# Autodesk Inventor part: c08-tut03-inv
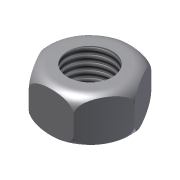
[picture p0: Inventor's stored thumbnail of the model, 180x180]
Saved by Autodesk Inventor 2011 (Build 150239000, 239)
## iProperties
Created: 2010-03
Part Number: c08-tut03-inv
Document SubType Name: Modeling
Designer: CADSoft
Density: 1 g/cm^3
Author: CADSoft
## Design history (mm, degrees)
sketch "Sketch1"
  geometry: C1 r 10 at (0, 0); 1 further point
  constraints: 1 centre point, 1 coincident
  dimensions: "d0" = 20 diameter of C1
extrude "Extrusion1" new body sketch "Sketch1" distance "d1" = 10; taper "d2" = 0 deg
hole "Hole1" diameter "d5" = 10; stored, may be unused: countersink angle "d9" = 90 deg, drill point angle "d11" = 118 deg; dims "d3" = 10, "d4" = 10, "d6" = 6, "d7" = 4, "d8" = 2, "d10" = 8
fillet "Fillet1" dims "d12" = 3, "d13" = 3
sketch "Sketch2"
  geometry: L1 (-10, 0)-(-5, 8.66); L2 (-5, 8.66)-(5, 8.66); L3 (5, 8.66)-(10, 0); L4 (10, 0)-(5, -8.66); L5 (5, -8.66)-(-5, -8.66); L6 (-5, -8.66)-(-10, 0); C1 r 5 at (0, 0); 1 further point
  constraints: 12 end point, 1 centre point, 1 coincident, 13 other
  dimensions: "d19" = 10 diameter of C1
extrude "Extrusion4" sketch "Sketch2" distance "d20" = 10; taper "d21" = 0 deg
thread "Thread1" dims "d22" = 10, "d23" = 0
body "Solid1"
